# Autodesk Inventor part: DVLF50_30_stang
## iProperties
Created: 2010-03
Part Number: DVLF50_30_stang
Document SubType Name: Modeling
Designer: TB
Mass: 213.756 g
Surface Area: 283.153 cm^2
Volume: 213.756 cm^3
Density: 1 g/cm^3
Author: TB
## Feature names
1. Revolution1
2. Fillet1
3. Revolution2
